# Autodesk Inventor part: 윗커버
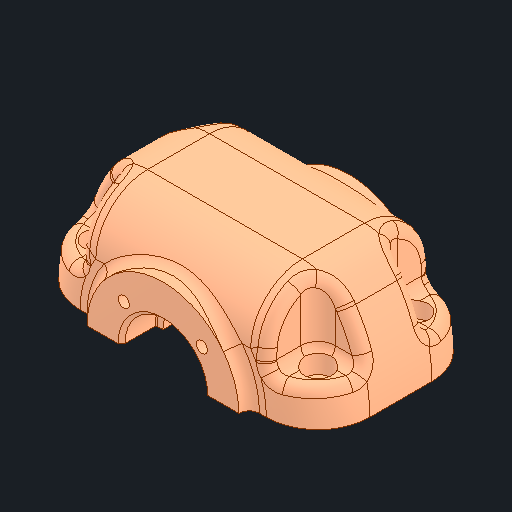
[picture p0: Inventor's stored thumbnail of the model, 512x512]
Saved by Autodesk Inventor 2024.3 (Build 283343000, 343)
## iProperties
Created: 2024-05
Part Number: 윗커버
Material: 알루미늄 6061
Document SubType Name: Modeling
Designer: MyPc
Density: 2.7 g/cm^3
Appearance: 기본값
Author: jhkim
Sending System: Autodesk Inventor 2025
Preprocessor: ST-DEVELOPER v20
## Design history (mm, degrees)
node "윗커버1"
node "솔리드2"
node "솔리드1"
